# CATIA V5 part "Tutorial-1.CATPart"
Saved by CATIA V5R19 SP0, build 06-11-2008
Part number: Part1
Bounding box of the stored display mesh (mm): x -175 to 175, y -250 to 250, z -8 to 100
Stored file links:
  D:\Shriniwas\v5_r19\Part files\c08\tut1.CATPart
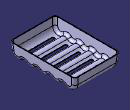
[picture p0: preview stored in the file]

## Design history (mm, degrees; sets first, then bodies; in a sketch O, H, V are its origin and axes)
Body1 (main body)
  Sketch1 on yz-plane, origin (0, 0, 0), H (0, 1, 0), V (0, 0, 1)
    line L1 (250, 100) -> (250, 0)
    line L2 (250, 0) -> (-250, 0)
    line L3 (-250, 0) -> (-250, 100)
    line L4 (-250, 100) -> (250, 100)
    length L1 = 100
    length L4 = 500
    distance V L1 = 250
    vertical: L1 V, L3 V
    horizontal: L2 H, L4 H
    coincidence: H L2
  Pad1: profile Sketch1, direction (1, 0, 0), length 175, mirrored extent
  Draft1: Angle 5, PullDir face of Pad1 from Sketch1.L4, Neutral face of Pad1 from Sketch1.L4
  Sketch2 on yz-plane, origin (0, 0, 0), H (0, 1, 0), V (0, 0, 1)
    arc A1 centre (-195.4346, 50) radius 50 from (-245.2443, 45.6422) to (-162.8621, 12.0654) ccw
    reference projected line E1 (-236.9099, -49.6202) -> (-245.6588, 50.3798) from edge [end face of Pad1 | face of Pad1 from Sketch1.L3]
    reference projected line E2 (241.2511, 0) -> (-241.2511, 0) from edge [end face of Pad1 | face of Pad1 from Sketch1.L2]
    arc A2 centre (195.4346, 50) radius 50 from (162.8621, 12.0654) to (245.2443, 45.6422) ccw
    reference projected line E3 (241.2511, 0) -> (-241.2511, 0) from edge [end face of Pad1 | face of Pad1 from Sketch1.L2]
    reference projected line E4 (245.6588, 50.3798) -> (236.9099, -49.6202) from edge [end face of Pad1 | face of Pad1 from Sketch1.L1]
    arc A3 centre (-146.5759, -6.902) radius 25 from (-162.8621, 12.0654) to (-130.2897, 12.0654) cw
    arc A4 centre (-48.8586, -6.902) radius 25 from (-65.1449, 12.0654) to (-32.5724, 12.0654) cw
    point P9 (-48.8586, -6.902)
    arc A5 centre (48.8586, -6.902) radius 25 from (32.5724, 12.0654) to (65.1449, 12.0654) cw
    point P12 (48.8586, -6.902)
    arc A6 centre (146.5759, -6.902) radius 25 from (130.2897, 12.0654) to (162.8621, 12.0654) cw
    construction line L1 (-146.5759, -6.902) -> (146.5759, -6.902)
    point P18 (245.2443, 45.6422)
    arc A7 centre (97.7173, 50) radius 50 from (65.1449, 12.0654) to (130.2897, 12.0654) ccw
    arc A8 centre (0, 50) radius 50 from (-32.5724, 12.0654) to (32.5724, 12.0654) ccw
    point P19 (-245.2443, 45.6422)
    arc A9 centre (-97.7173, 50) radius 50 from (-130.2897, 12.0654) to (-65.1449, 12.0654) ccw
    reference projected line E5 (245.6588, 50.3798) -> (236.9099, -49.6202) from edge [end face of Pad1 | face of Pad1 from Sketch1.L1]
    reference projected line E6 (-236.9099, -49.6202) -> (-245.6588, 50.3798) from edge [end face of Pad1 | face of Pad1 from Sketch1.L3]
    reference projected line E7 (241.2511, 0) -> (-241.2511, 0) from edge [end face of Pad1 | face of Pad1 from Sketch1.L2]
    reference projected line E8 (241.2511, 0) -> (-241.2511, 0) from edge [end face of Pad1 | face of Pad1 from Sketch1.L2]
    reference projected line E9 (241.2511, 0) -> (-241.2511, 0) from edge [end face of Pad1 | face of Pad1 from Sketch1.L2]
    radius A3 = 25
    radius A4 = 25
    radius A5 = 25
    radius A6 = 25
    radius A9 = 50
    radius A8 = 50
    radius A7 = 50
    radius A1 = 50
    radius A2 = 50
    tangency: A1 E1, A1 E2, A2 E3, A2 E4, A3 A1, A6 A2, A3 A9, A4 A8, A4 A9, A8 A5, A5 A7, A7 A6, A9 E7, A7 E8, A8 E9
    coincidence: L1 P12, P9 L1, P18 E5, P19 E6
    horizontal: L1 H
  Pocket1: profile Sketch2, direction (-1, 0, 0), through (limit type 3), opposite side through (limit type 3)
  Fillet1: radius 25, on edge [end face of Pad1 | face of Pocket1]; edge [face of Pocket1 | start face of Pad1]
  Shell1: ExtOffset 0, IntOffset 5, Face face of Pad1 from Sketch1.L4
  Sketch3 on xy-plane, origin (0, 0, 0), H (1, 0, 0), V (0, 1, 0)
    construction line L1 (-105, 195.4346) -> (105, 195.4346)
    point P1 (-105, 195.4346)
    line L2 (-105, 207.4346) -> (105, 207.4346)
    line L3 (105, 183.4346) -> (-105, 183.4346)
    arc A1 centre (105, 195.4346) radius 12 from (105, 207.4346) to (105, 183.4346) cw
    arc A2 centre (-105, 195.4346) radius 12 from (-105, 183.4346) to (-105, 207.4346) cw
    reference projected line E1 through (0, 195.4346) direction (1, 0) from axis of face of Shell1
    length L1 = 210
    distance V P1 = 105
    distance L3 L2 = 24
    horizontal: L1 H
    tangency: A1 L2, A2 L2, A1 L3, A2 L3
    coincidence: E1 L1
  Pocket2: profile Sketch3, direction (0, 0, 1), through (limit type 6)
  RectPattern1: of Pocket2, direction 1 instances 5, spacing 97.717, along edge [face of Shell1 | face of Pad1 from Sketch1.L4]
  Sketch4 on xy-plane, origin (0, 0, 0), H (1, 0, 0), V (0, 1, 0)
    circle A1 centre (-135, -195.4346) radius 10
    point P1 (-135, -195.4346)
    reference projected line E1 through (0, -195.4346) direction (1, 0) from axis of face of Shell1
    reference projected line E2 (-175, 250) -> (-175, -250) from edge [start face of Pad1 | face of Pad1 from Sketch1.L4]
    radius A1 = 10
    distance P1 E2 = 40
    coincidence: E1 P1
  Pad2: profile Sketch4, direction (0, 0, 1), up to the existing solid (limit type 2), opposite side length 8
  RectPattern2: of Pad2, direction 1 instances 2, spacing 390.868, along edge [start face of Pad1 | face of Pad1 from Sketch1.L4] reversed, direction 2 instances 2, spacing 270, along edge [face of Pad1 from Sketch1.L3 | face of Pad1 from Sketch1.L4]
